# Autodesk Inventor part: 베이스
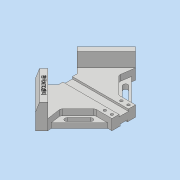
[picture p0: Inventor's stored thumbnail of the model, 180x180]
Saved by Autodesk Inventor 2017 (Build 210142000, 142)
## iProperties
Part Number: 베이스
Material: 일반
Document SubType Name: Modeling
Designer: 00-00
Density: 1 g/cm^3
Appearance: 기본값
Mass: 211.693 g
Surface Area: 407.229 cm^2
Volume: 211.693 cm^3
Author: 00-00
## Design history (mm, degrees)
sketch "스케치1"
  geometry: L1 (0, 84.853)-(84.853, 0); L2 (84.853, 0)-(0, -84.853); L3 (0, -84.853)-(-84.853, 0); L4 (-84.853, 0)-(0, 84.853); L5 (0, 84.853)-(0, -84.853); L6 (84.853, 0)-(-84.853, 0); L7 (0, 84.853)-(120, 84.853); L8 (-10.607, 74.246)-(-7.071, 49.497); L9 (-7.071, 49.497)-(-36.569, 20); L10 (-36.569, 20)-(-64.853, 20); L11 (-64.853, -20)-(-36.569, -20); L12 (-36.569, -20)-(-7.071, -49.497); L13 (-7.071, -49.497)-(-10.607, -74.246); L14 (49.497, 35.355)-(30.147, 16.005); L15 (30.147, 16.005)-(30.147, -16.005); L16 (30.147, -16.005)-(49.497, -35.355); L17 (-64.853, 20)-(-64.853, -20); L18 (-7.071, 49.497)-(-21.213, 63.64); L19 (-7.071, -49.497)-(-21.213, -63.64); L20 (49.497, 35.355)-(0, 84.853); L21 (-10.607, 74.246)-(0, 84.853); L22 (-10.607, -74.246)-(0, -84.853); L23 (0, -84.853)-(49.497, -35.355); 5 further points
  constraints: 46 end point, 9 point on line, 6 perpendicular, 5 midpoint, 5 parallel, 2 horizontal alignment, 2 vertical, 1 collinear, 1 equal length, 1 horizontal
  dimensions: "d0" = 120 distance of L1.start L1.end; "d1" = 45 deg angle of L1 L7; "d2" = 120 distance of L1.end L2.end; "d3" = 20 distance between parallel lines of L4 L9; "d4" = 20 distance between parallel lines of L3 L12; "d5" = 15 distance of L2.end L13.end; "d6" = 15 distance of L1.start L8.start; "d8" = 50 distance of L1.end L14.start; "d9" = 50 distance of L16.end L1.end; "d10" = 20 distance from line of L17 L3.end; "d11" = 95 distance between parallel lines of L17 L15; "d12" = 30 distance from line of L18.end L1; "d14" = 30 distance between parallel lines of L2 L19
extrude "돌출1" new body sketch "스케치1" distance "d16" = 18; taper "d17" = 0 deg
sketch "스케치2"
  geometry: L1 (-49.497, 35.355)-(0, 84.853) reference; L2 (-30.147, 16.005)-(-49.497, 35.355) reference; L3 (0, 84.853)-(10.607, 74.246) reference; L4 (-49.497, 35.355)-(0, 84.853); L5 (0, 84.853)-(10.607, 74.246); L6 (10.607, 74.246)-(-38.891, 24.749); L7 (-38.891, 24.749)-(-49.497, 35.355); L8 (-49.497, -35.355)-(-30.147, -16.005) reference; L9 (0, -84.853)-(-49.497, -35.355) reference; L10 (10.607, -74.246)-(0, -84.853) reference; L11 (-49.497, -35.355)-(0, -84.853); L12 (0, -84.853)-(10.607, -74.246); L13 (10.607, -74.246)-(-38.891, -24.749); L14 (-38.891, -24.749)-(-49.497, -35.355); 1 further point
  constraints: 16 end point, 4 parallel, 3 perpendicular
  dimensions: "d18" = 15 distance of L12.end L9.start; "d19" = 15 distance between parallel lines of L6 L1
extrude "돌출2" join sketch "스케치2" distance "d20" = 42; taper "d21" = 0 deg
sketch "스케치3"
  geometry: L1 (0, 42)-(5, 42); L2 (5, 42)-(0, 27); L3 (0, 27)-(0, 42); 2 further points
  constraints: 6 end point, 1 coincident, 1 horizontal, 1 perpendicular
  dimensions: "d22" = 5 distance of L1.start L1.end; "d23" = 15 distance of L2.end L1.start
extrude "돌출3" cut sketch "스케치3" stored distance "d24" = 42; taper "d25" = 0 deg
sketch "스케치4" dims "d19" = 15
  geometry: L1 (-5, 42)-(0, 42); L2 (0, 42)-(0, 27); L3 (0, 27)-(-5, 42); 2 further points
  constraints: 6 end point, 1 coincident, 1 horizontal, 1 perpendicular
  dimensions: "d26" = 5 distance of L1.start L1.end; "d27" = 15 distance of L1.end L2.end
extrude "돌출4" cut sketch "스케치4" stored distance "d28" = 42; taper "d29" = 0 deg
sketch "스케치5"
  geometry: L1 (10.607, 74.246)-(7.071, 49.497) reference; L2 (36.569, 20)-(64.853, 20) reference; L3 (36.569, -20)-(7.071, -49.497) reference; L4 (7.071, 49.497)-(10.607, 74.246) reference; L5 (9.723, 68.059)-(7.071, 49.497); L6 (9.723, 68.059)-(57.782, 20); L7 (57.782, -20)-(9.723, -68.059); L8 (36.569, 20)-(57.782, 20); L9 (36.569, -20)-(57.782, -20); L10 (7.071, -49.497)-(36.569, -20); L11 (7.071, -49.497)-(10.607, -74.246) reference; L12 (7.071, -49.497)-(9.723, -68.059); L13 (7.071, 49.497)-(36.569, 20) reference; L14 (7.071, 49.497)-(36.569, 20); L15 (18.385, 49.497)-(38.184, 29.698); L16 (15.556, 46.669)-(35.355, 26.87); L17 (41.012, 32.527)-(21.213, 52.326); L18 (0, 84.853)-(-49.497, 35.355) reference; L19 (3.536, 81.317)-(0, 84.853) reference; L20 (0, 0)-(73.539, 0); L21 (15.556, -46.669)-(35.355, -26.87); L22 (41.012, -32.527)-(21.213, -52.326); A1 r 4 centre (18.385, 49.497) between (21.213, 52.326) and (15.556, 46.669); A2 r 4 centre (38.184, 29.698) between (35.355, 26.87) and (41.012, 32.527); A3 r 4 centre (18.385, -49.497) between (15.556, -46.669) and (21.213, -52.326); A4 r 4 centre (38.184, -29.698) between (41.012, -32.527) and (35.355, -26.87); 1 further point
  constraints: 30 end point, 8 point on circle, 6 symmetric about line, 5 collinear, 4 centre point, 4 tangent, 3 parallel, 3 point on line, 2 horizontal, 1 midpoint, 2 other
  dimensions: "d31" = 15 distance between parallel lines of L3 L7; "d32" = 15 distance between parallel lines of L6 L13; "d33" = 28 distance of L15.end L15.start; "d34" = 38 distance from line of L18 L15.start; "d35" = 8 distance of L16.end L17.start; "d36" = 12 distance from line of L15.start L19
extrude "돌출5" join sketch "스케치5" distance "d37" = 8; taper "d38" = 0 deg
sketch "스케치6"
  geometry: L1 (12, 14.5)-(28, 14.5); L2 (28, 14.5)-(28, 18); L3 (28, 18)-(12, 18); L4 (12, 18)-(12, 14.5); L5 (40, 0)-(0, 0) reference; L6 (14, 3)-(26, 3); L7 (26, 3)-(26, 0); L8 (26, 0)-(14, 0); L9 (14, 0)-(14, 3); 7 further points
  constraints: 16 end point, 5 midpoint, 4 parallel, 2 coincident, 2 horizontal, 2 perpendicular, 1 horizontal alignment, 1 vertical alignment
  dimensions: "d39" = 16 distance of L3.end L2.end; "d40" = 3.5 distance of L2.end L1.end; "d41" = 12 distance of L7.end L8.end; "d42" = 3 distance of L6.end L7.end
extrude "돌출6" cut sketch "스케치6" stored distance "d43" = 8; taper "d44" = 0 deg
sketch "스케치7"
  geometry: L1 (64.853, 6)-(64.853, 20) reference; 5 further points
  constraints: 2 horizontal alignment, 2 vertical alignment
  dimensions: "d45" = 12 distance of point (58.853, 14) point (46.853, 14); "d46" = 6 distance from line of L1 point (58.853, 14); "d47" = 28 distance of point (58.853, 14) point (58.853, -14); "d48" = 14 vertical distance of point (46.853, 14) point (0, 0)
hole "구멍1" sketch "스케치7" at (46.853, -14), (46.853, 14), (58.853, 14), (58.853, -14) diameter "d49" = 4.5; stored, may be unused: countersink angle "d53" = 90 deg, drill point angle "d55" = 118 deg; dims "d50" = 6, "d51" = 8, "d52" = 10, "d54" = 8
fillet "모깎기1" dims "d56" = 5
sketch "스케치8"
  geometry: L1 (-38.891, -24.749)-(-45.962, -31.82) reference; L2 (10.607, -74.246)-(-38.891, -24.749) reference; 2 further points
  constraints: 1 other
  dimensions: "d57" = 35 distance from line of point (-17.678, -53.033) L1; "d58" = 5 distance from line of L2 point (-17.678, -53.033)
feature "엠보싱1" sketch "스케치8" dims "d0" = 120, "d1" = 45 deg, "d2" = 120, "d3" = 20, "d4" = 20, "d5" = 15, "d6" = 15, "d8" = 50, "d9" = 50, "d10" = 20, "d11" = 95, "d12" = 30, "d14" = 30, "d16" = 18, "d59" = 0.5, "d60" = 0
node "솔리드1"
